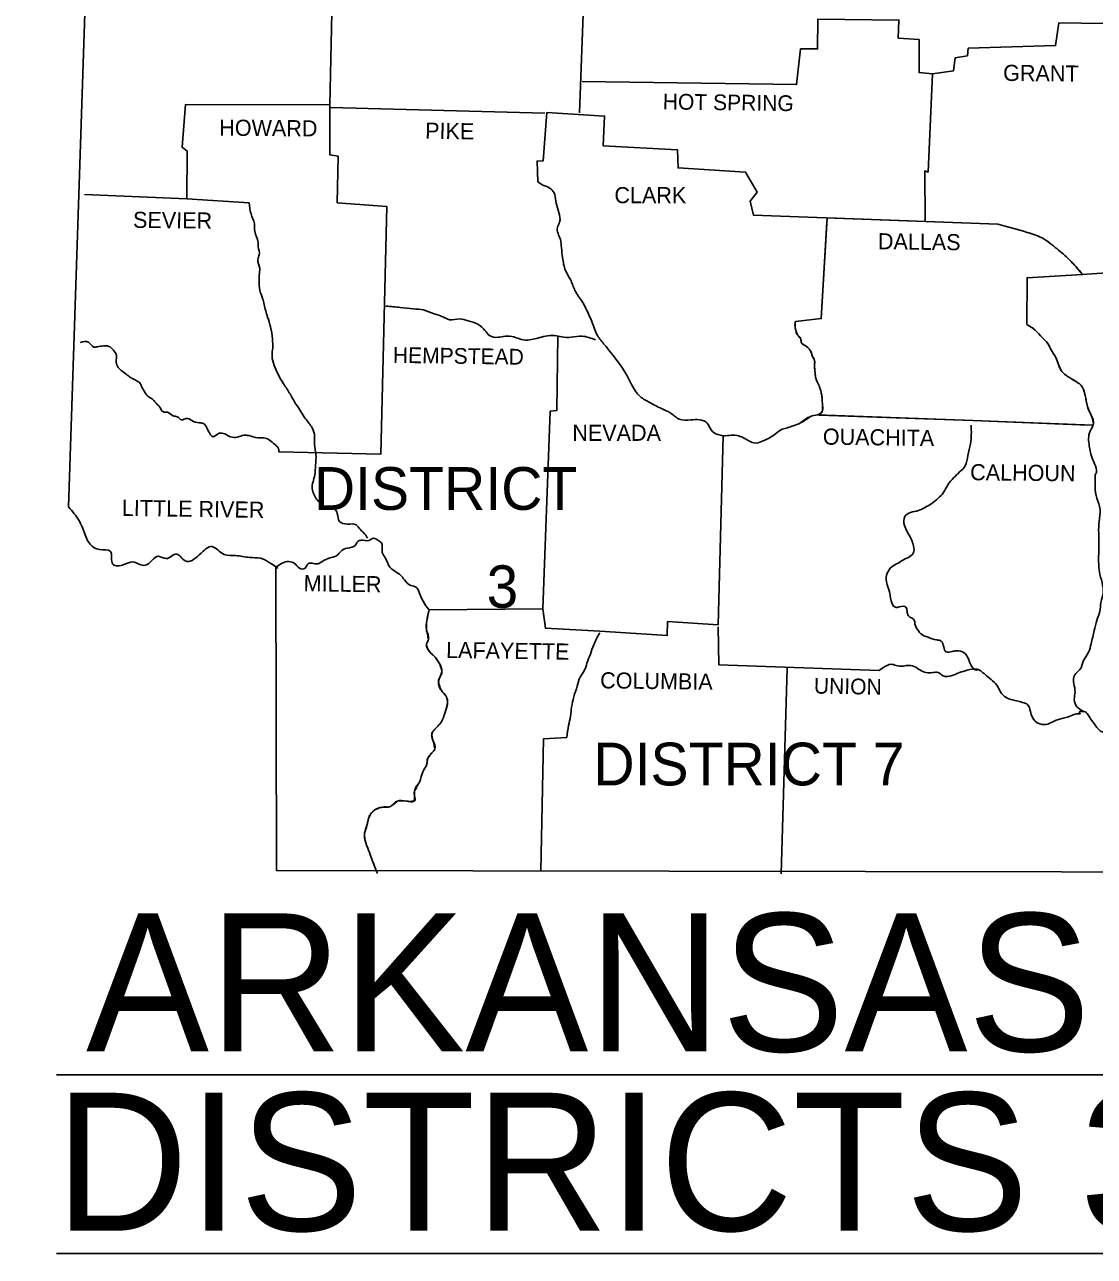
# Model space of a CAD drawing. Extents: x -35254 to 17396, y -8913 to 11592.
# Drawn here: x 11395 to 14186, y 3738 to 6952 of the extents above; entities that cross this region are included whole.
import ezdxf

# ---------------------------------------------------------------- set-up
doc = ezdxf.new("R2010")
doc.units = 0
for name, color, linetype in [('1', 7, 'Continuous'), ('2', 7, 'Continuous'), ('3', 7, 'Continuous'), ('S_MISC_BOUNDARY', 7, 'Continuous')]:
    doc.layers.add(name, color=color, linetype=linetype)

msp = doc.modelspace()

# ---------------------------------------------------------------- linework, layer by layer
at = {"layer": '1'}
for p, q in [((11477.4, 4211.6), (15730.4, 4211.6)), ((11477.4, 3744.7), (15730.4, 3744.7))]:
    msp.add_line(p, q, dxfattribs=at)
for points in [[(11394.6, 9973.9), (11597.1, 8347.8), (11509, 5693.4)], [(12865.1, 7331.3), (12842.6, 6721.7)], [(12201.7, 7223.6), (12191, 6742.3), (11814.3, 6743.2), (11805.5, 6631.7), (11819.2, 6621.9), (11818.2, 6496.7), (11551.1, 6508.4)], [(12849.5, 6802.9), (13409.1, 6795.1), (13419.9, 6888.1), (13463.9, 6888.1), (13464.9, 6966.3), (13676.2, 6963.4), (13674.2, 6916.4), (13729, 6912.5), (13729, 6826.4), (13764.3, 6823.5)], [(13764.3, 6823.5), (13819.1, 6831.3), (13823, 6864.6), (13855.3, 6870.4), (13857.2, 6890), (14085.2, 6896.9), (14094, 6956.5), (14327.8, 6952.6)], [(13764.3, 6823.5), (13752.5, 6567.1), (13743.7, 6570.1), (13744.7, 6437)], [(12191, 6742.3), (12191, 6612.1), (12212.5, 6608.2), (12210.6, 6486.9), (12339.7, 6477.1), (12324, 5830.4), (12057.9, 5837.2)], [(12192.9, 6735.4), (12752.6, 6720.7)], [(12734, 6541.7), (12732, 6595.5), (12747.7, 6596.5), (12757.5, 6722.7), (12908.2, 6712.9), (12904.2, 6635.6), (13098.9, 6624.9), (13099.9, 6577.9), (13276, 6567.1), (13306.4, 6514.3), (13287.8, 6490.8), (13296.6, 6454.6), (13934.5, 6431.1)], [(11818.2, 6496.7), (11980.6, 6486.9)], [(13488.4, 6436), (13473.7, 6184.6), (13406.2, 6176.7)], [(14155.6, 6300), (14010.8, 6291.2), (14009.8, 6168.9)], [(14296.5, 6308.8), (14153.7, 6300)], [(12785.9, 6139.6), (12783.9, 5944.9), (12766.3, 5942.9), (12746.7, 5427.3)], [(13463.9, 5933.1), (13869, 5918.4), (14169.3, 5906.7)], [(13217.3, 5878.3), (13204.6, 5385.2), (13072.5, 5394), (13071.6, 5357.8), (12895.4, 5368.6)], [(12050.1, 5535.9), (12052.1, 4744.4), (15637.9, 4738.5)], [(12895.4, 5368.6), (12753.6, 5376.4), (12746.7, 5427.3), (12450.3, 5424.4)], [(13624.4, 5265.9), (13206.6, 5281.5), (13204.6, 5380.3)], [(13384.6, 5272.7), (13369, 4735.6)], [(12809.3, 5091.7), (12748.7, 5087.8), (12741.8, 4743.4)]]:
    msp.add_lwpolyline(points, dxfattribs=at)
for points in [[(12734, 6541.7), (12749.7, 6531.9), (12768.2, 6523.1), (12778, 6508.4), (12781.9, 6485.9), (12788.8, 6461.5), (12790.7, 6436), (12784.9, 6422.3), (12792.7, 6391), (12795.6, 6369.5), (12798.6, 6344.1), (12806.4, 6309.8), (12819.1, 6286.3), (12830.9, 6258), (12850.4, 6227.6), (12867.1, 6194.4), (12874.9, 6176.7), (12889.6, 6140.5), (12908.2, 6116.1), (12937.5, 6078.9), (12963.9, 6040.8), (12978.6, 6012.4), (13001.1, 5981.1), (13026.5, 5965.4), (13058.8, 5948.8), (13079.4, 5939), (13102.9, 5922.4), (13133.2, 5920.4), (13155.7, 5920.4), (13176.2, 5911.6), (13186, 5894), (13203.6, 5882.2), (13217.3, 5878.3)], [(11980.6, 6486.9), (11985.5, 6457.6), (11994.3, 6432.1), (11995.3, 6412.5), (12004.1, 6383.2), (12004.1, 6372.4), (12007, 6350.9), (12003.1, 6339.2), (12008, 6315.7), (12007, 6298.1), (12007, 6283.4), (12008, 6258.9), (12015.8, 6237.4), (12023.7, 6205.1), (12028.6, 6188.5), (12036.4, 6163.1), (12041.3, 6131.7), (12042.3, 6108.3), (12040.3, 6086.7), (12046.2, 6062.3), (12056.9, 6037.8), (12070.6, 6014.3), (12087.3, 5987.9), (12099, 5967.4), (12113.7, 5944.9), (12125.4, 5926.3), (12143, 5902.8), (12150.9, 5883.2), (12150.9, 5855.8), (12154.8, 5830.4), (12153.8, 5802), (12151.8, 5776.6), (12145, 5741.4), (12149.9, 5724.7), (12168.5, 5700.3), (12180.2, 5693.4), (12200.8, 5689.5), (12210.6, 5675.8), (12216.4, 5655.3), (12237, 5648.4), (12259.5, 5646.5), (12270.2, 5634.7), (12284.9, 5619.1), (12289.8, 5611.2)], [(13934.5, 6431.1), (14010.8, 6409.6), (14050, 6394.9), (14089.1, 6366.6), (14121.4, 6338.2), (14153.7, 6302)], [(12337.7, 6216.9), (12374.9, 6213.9), (12409.2, 6210), (12435.6, 6207.1), (12463, 6197.3), (12487.4, 6188.5), (12503.1, 6181.6), (12529.5, 6183.6), (12552, 6178.7), (12577.5, 6169.9), (12596, 6153.3), (12607.8, 6140.5), (12630.3, 6135.7), (12648.9, 6138.6), (12671.4, 6136.6), (12696.8, 6128.8), (12717.4, 6129.8), (12734, 6133.7), (12753.6, 6138.6), (12778, 6140.5), (12796.6, 6136.6), (12821.1, 6135.7), (12849.5, 6138.6), (12884.7, 6128.8)], [(13406.2, 6176.7), (13406.2, 6158.2), (13413, 6140.5), (13419.9, 6132.7), (13422.8, 6120), (13431.6, 6114.1), (13444.3, 6102.4), (13451.2, 6085.8), (13456.1, 6075), (13456.1, 6061.3), (13457, 6047.6), (13459, 6031), (13470.7, 6001.6), (13473.7, 5989.9), (13475.6, 5980.1), (13476.6, 5963.5), (13476.6, 5943.9), (13463.9, 5933.1)], [(14009.8, 6168.9), (14032.3, 6154.2), (14050.9, 6134.7), (14064.6, 6120), (14073.4, 6103.4), (14085.2, 6083.8), (14101.8, 6046.6), (14116.5, 6033.9), (14137, 6021.2), (14149.8, 6012.4), (14162.5, 5984), (14168.3, 5955.6), (14179.1, 5930.2), (14184, 5910.6), (14175.2, 5891.1), (14173.2, 5851.9), (14179.1, 5825.5), (14186.9, 5805.9), (14191.8, 5783.4), (14188.9, 5776.6)], [(11539.4, 6122), (11560.9, 6122.9), (11575.6, 6110.2), (11584.4, 6111.2), (11600, 6113.2), (11614.7, 6112.2), (11625.5, 6103.4), (11634.3, 6087.7), (11633.3, 6073), (11634.3, 6067.2), (11641.1, 6054.4), (11652.9, 6044.7), (11665.6, 6034.9), (11677.3, 6027.1), (11696.9, 6014.3), (11698.8, 6010.4), (11706.7, 5994.8), (11716.5, 5982), (11728.2, 5974.2), (11740.9, 5960.5), (11746.8, 5954.7), (11756.6, 5941), (11767.3, 5940), (11782, 5931.2), (11792.8, 5928.2), (11804.5, 5920.4), (11816.3, 5924.3), (11830.9, 5918.4), (11850.5, 5912.6), (11861.3, 5910.6), (11874, 5892), (11886.7, 5876.4), (11902.4, 5885.2), (11931.7, 5876.4), (11950.3, 5875.4), (11966.9, 5880.3), (11979.6, 5879.3), (12003.1, 5873.4), (12017.8, 5873.4), (12033.5, 5867.6), (12048.1, 5855.8), (12057.9, 5843.1), (12057.9, 5837.2)], [(13445.3, 5929.2), (13419.9, 5912.6), (13400.3, 5904.8), (13385.6, 5899.9), (13371.9, 5895.9), (13354.3, 5884.2), (13340.6, 5874.4), (13322, 5865.6), (13304.4, 5859.7), (13282.9, 5866.6), (13271.1, 5873.4), (13258.4, 5878.3), (13217.3, 5878.3)], [(13419.9, 5912.6), (13445.3, 5929.2), (13463.9, 5933.1)], [(13865, 5906.7), (13863.1, 5857.8), (13856.2, 5827.5), (13849.4, 5800.1), (13834.7, 5784.4), (13819.1, 5768.8), (13804.4, 5751.1), (13791.7, 5729.6), (13778.9, 5715.9), (13762.3, 5702.2), (13745.7, 5692.4), (13727.1, 5683.6), (13706.5, 5678.7), (13691.9, 5668), (13690.9, 5644.5), (13707.5, 5611.2), (13713.4, 5595.6), (13715.3, 5577), (13708.5, 5566.2), (13692.8, 5557.4), (13674.2, 5546.7), (13657.6, 5536.9), (13645.9, 5520.2), (13643.9, 5497.7), (13651.7, 5471.3), (13654.7, 5455.7), (13667.4, 5431.2), (13677.2, 5432.2), (13694.8, 5431.2), (13696.8, 5426.3), (13697.7, 5421.4), (13701.6, 5408.7), (13716.3, 5397.9), (13718.3, 5388.2), (13727.1, 5369.6), (13741.8, 5356.8), (13752.5, 5352.9), (13775, 5346.1), (13786.8, 5343.1), (13799.5, 5314.8), (13815.1, 5315.8), (13826.9, 5317.7), (13846.4, 5312.8), (13855.3, 5301.1), (13864.1, 5281.5), (13875.8, 5267.8), (13883.6, 5267.8)], [(14188.9, 5776.6), (14192.8, 5715.9), (14201.6, 5686.6), (14198.7, 5655.3), (14197.7, 5624.9), (14197.7, 5597.5), (14197.7, 5571.1), (14197.7, 5543.7), (14199.7, 5524.2), (14206.5, 5495.8), (14209.4, 5469.4), (14203.6, 5443.9), (14200.6, 5420.4), (14192.8, 5397), (14186, 5370.5), (14178.1, 5336.3), (14171.3, 5313.8), (14157.6, 5290.3), (14148.8, 5268.8), (14135.1, 5255.1), (14133.1, 5231.6), (14136.1, 5210.1), (14134.1, 5190.5), (14140.9, 5171.9), (14158.6, 5159.2)], [(11509, 5693.4), (11537.4, 5656.2), (11549.1, 5629.8), (11565.8, 5595.6), (11590.2, 5581.9), (11618.6, 5577), (11624.5, 5543.7), (11653.8, 5542.7), (11677.3, 5549.6), (11709.6, 5540.8), (11743.9, 5564.3), (11763.4, 5558.4), (11791.8, 5570.1), (11813.3, 5552.5), (11850.5, 5568.2), (11883.8, 5589.7), (11915.1, 5569.2), (11945.4, 5566.2), (11981.6, 5561.3), (12010, 5559.4), (12035.4, 5546.7), (12054, 5533.9), (12050.1, 5535.9)], [(12050.1, 5535.9), (12084.3, 5550.6), (12099, 5545.7), (12111.7, 5533), (12126.4, 5533), (12134.2, 5544.7), (12148.9, 5545.7), (12160.7, 5544.7), (12173.4, 5552.5), (12184.1, 5557.4), (12198.8, 5562.3), (12209.6, 5566.2), (12219.4, 5577), (12237, 5585.8), (12257.5, 5592.6), (12263.4, 5602.4), (12273.2, 5606.3), (12292.7, 5605.4), (12305.5, 5611.2), (12316.2, 5606.3), (12326, 5599.5), (12328, 5574.1), (12335.8, 5560.4), (12347.5, 5535.9), (12364.2, 5523.2), (12379.8, 5510.5), (12385.7, 5502.6), (12402.3, 5488), (12417, 5483.1), (12423.8, 5472.3), (12434.6, 5446.9), (12450.3, 5424.4)], [(12450.3, 5424.4), (12444.4, 5396), (12443.4, 5373.5), (12448.3, 5347.1), (12443.4, 5334.3), (12451.2, 5315.8), (12465.9, 5301.1), (12476.7, 5285.4), (12483.5, 5262.9), (12474.7, 5237.5), (12484.5, 5211.1), (12493.3, 5201.3), (12498.2, 5185.6), (12491.4, 5155.3), (12482.5, 5132.8), (12463, 5110.3), (12457.1, 5099.5), (12460, 5084.8), (12464.9, 5061.4), (12460, 5054.5), (12447.3, 5037.9), (12443.4, 5019.3), (12434.6, 5003.6), (12424.8, 4975.3), (12412.1, 4951.8), (12410.1, 4925.4), (12390.6, 4925.4), (12368.1, 4925.4), (12347.5, 4910.7), (12328.9, 4909.7), (12306.4, 4900.9), (12292.7, 4882.3), (12287.8, 4861.8), (12282, 4842.2), (12287.8, 4808.9), (12296.7, 4785.5), (12303.5, 4766.9), (12315.2, 4736.5)], [(12809.3, 5091.7), (12814.2, 5123), (12819.1, 5147.5), (12822.1, 5170.9), (12827.9, 5197.4), (12836.7, 5225.7), (12844.6, 5249.2), (12855.3, 5265.9), (12862.2, 5285.4), (12871, 5308.9), (12879.8, 5333.4), (12895.4, 5364.7)], [(13624.4, 5265.9), (13640, 5276.6), (13654.7, 5282.5), (13669.4, 5279.5), (13685, 5277.6), (13698.7, 5279.5), (13716.3, 5276.6), (13731, 5267.8), (13747.6, 5261), (13764.3, 5261), (13778.9, 5261), (13791.7, 5252.2), (13815.1, 5253.1), (13834.7, 5261), (13854.3, 5266.8), (13880.7, 5269.8), (13904.2, 5253.1), (13920.8, 5239.4), (13934.5, 5223.8), (13944.3, 5206.2), (13955.1, 5196.4), (13972.7, 5189.5), (13986.4, 5186.6), (14003, 5181.7), (14011.8, 5177.8), (14019.6, 5159.2), (14032.3, 5133.8), (14056.8, 5125), (14087.1, 5136.7), (14111.6, 5143.6), (14129.2, 5149.4), (14140, 5153.3), (14149.8, 5154.3), (14146.8, 5156.3), (14158.6, 5159.2), (14169.3, 5151.4), (14176.2, 5140.6), (14187.9, 5125), (14198.7, 5111.3), (14209.4, 5106.4), (14220.2, 5112.2), (14234.9, 5107.4), (14247.6, 5102.5), (14262.3, 5098.5), (14275, 5097.6), (14291.6, 5093.7), (14304.3, 5086.8), (14316.1, 5080), (14327.8, 5067.2), (14339.6, 5047.7), (14343.5, 5032), (14357.2, 5016.4), (14369.9, 5016.4), (14388.5, 4990.9), (14395.3, 4981.1), (14410, 4963.5), (14420.8, 4963.5), (14441.3, 4959.6)]]:
    msp.add_spline(points, degree=3, dxfattribs=at)
at = {"layer": 'S_MISC_BOUNDARY'}
for points in [[(13934.5, 6431.1), (13489, 6447.5), (13473.7, 6184.6), (13406.2, 6176.7)], [(14009.8, 6168.9), (14010.8, 6291.2), (14155.6, 6300)], [(13468.5, 5933), (13869, 5918.4), (14183.1, 5906.2)], [(12050.1, 5535.9), (12052.1, 4744.4), (12312.3, 4743.9)]]:
    msp.add_lwpolyline(points, dxfattribs=at)
for points in [[(14155.6, 6300), (14121.4, 6338.2), (14089.1, 6366.6), (14050, 6394.9), (14010.8, 6409.6), (13934.5, 6431.1)], [(13406.2, 6176.7), (13405.1, 6167.5), (13405.4, 6162.8), (13406.2, 6158.2), (13407.3, 6153.6), (13408.9, 6149.1), (13410.8, 6144.8), (13413, 6140.5), (13414.6, 6138.4), (13416.4, 6136.5), (13418.3, 6134.7), (13419.9, 6132.7), (13420.8, 6129.7), (13421, 6126.2), (13421.3, 6122.8), (13421.9, 6121.3), (13422.8, 6120), (13424.9, 6118.3), (13427.1, 6117), (13429.4, 6115.6), (13431.6, 6114.1), (13433.3, 6112.8), (13435.1, 6111.5), (13438.6, 6108.8), (13441.8, 6105.9), (13443.2, 6104.2), (13444.3, 6102.4), (13446.2, 6098.3), (13447.9, 6094.1), (13449.5, 6089.9), (13451.2, 6085.8), (13453.8, 6080.5), (13455, 6077.8), (13455.6, 6076.4), (13456.1, 6075), (13456.6, 6071.6), (13456.4, 6068.2), (13456.1, 6064.7), (13456.1, 6061.3), (13456.1, 6060.6)], [(14107, 6040.9), (14101.8, 6046.6), (14100.4, 6048.8), (14099.1, 6051), (14096.8, 6055.6), (14093, 6065.1), (14089.5, 6074.6), (14085.2, 6083.8), (14079.3, 6093.6), (14073.4, 6103.4), (14071.3, 6107.6), (14069.4, 6111.9), (14067.3, 6116.2), (14064.6, 6120), (14063, 6121.9), (14061.3, 6123.8), (14057.9, 6127.4), (14050.9, 6134.7), (14032.3, 6154.2), (14027.4, 6158.7), (14021.9, 6162.5), (14016.1, 6165.8), (14009.8, 6168.9)], [(13456.1, 6060.6), (13456.5, 6054.4), (13457, 6047.6), (13457.8, 6039.3), (13458.3, 6035.1), (13459, 6031), (13461.3, 6023.4), (13464.6, 6016.2), (13468, 6009), (13470.7, 6001.6), (13473.7, 5989.9), (13475.6, 5980.1), (13476, 5975.9), (13476.2, 5971.8), (13476.6, 5963.5), (13476.8, 5958.6), (13476.9, 5953.7), (13476.8, 5948.8), (13476.7, 5946.3), (13476.6, 5943.9), (13475.8, 5941.1), (13473.8, 5938.1), (13472.6, 5936.7), (13471.3, 5935.3), (13468.5, 5933)], [(14183.1, 5906.2), (14184, 5910.6), (14183.4, 5915.5), (14182.3, 5920.4), (14179.1, 5930.2), (14176.4, 5936.6), (14173.6, 5942.9), (14170.8, 5949.2), (14168.3, 5955.6), (14166.5, 5962.6), (14165.2, 5969.7), (14164.1, 5976.9), (14162.5, 5984), (14160.4, 5991.7), (14158.1, 5999.2), (14154.7, 6006.3), (14149.8, 6012.4), (14148.2, 6013.7), (14146.7, 6014.9), (14143.5, 6017.1), (14137, 6021.2), (14116.5, 6033.9), (14108.5, 6039.6), (14107, 6040.9)], [(12450.3, 5424.4), (12434.6, 5446.9), (12423.8, 5472.3), (12417, 5483.1), (12402.3, 5488), (12385.7, 5502.6), (12379.8, 5510.5), (12364.2, 5523.2), (12347.5, 5535.9), (12335.8, 5560.4), (12328, 5574.1), (12326, 5599.5), (12316.2, 5606.3), (12305.5, 5611.2), (12292.7, 5605.4), (12273.2, 5606.3), (12263.4, 5602.4), (12257.5, 5592.6), (12237, 5585.8), (12219.4, 5577), (12209.6, 5566.2), (12198.8, 5562.3), (12184.1, 5557.4), (12173.4, 5552.5), (12160.7, 5544.7), (12148.9, 5545.7), (12134.2, 5544.7), (12126.4, 5533), (12111.7, 5533), (12099, 5545.7), (12084.3, 5550.6), (12050.1, 5535.9)], [(12475.3, 5233.6), (12474.7, 5237.5), (12475.8, 5243.8), (12479.1, 5250.2), (12482.4, 5256.6), (12483.5, 5262.9), (12482.7, 5268.5), (12481.3, 5274.2), (12479.3, 5279.8), (12476.7, 5285.4), (12471.6, 5293.6), (12465.9, 5301.1), (12462.4, 5304.8), (12458.6, 5308.1), (12454.8, 5311.6), (12451.2, 5315.8), (12446, 5325), (12444.3, 5329.6), (12443.4, 5334.3), (12444, 5337.5), (12445.8, 5340.7), (12447.6, 5343.8), (12448.3, 5347.1), (12447.3, 5353.5), (12445.7, 5360.1), (12444.1, 5366.8), (12443.4, 5373.5), (12444.4, 5396), (12445.5, 5403.7), (12446.9, 5411.8), (12450.3, 5424.4)], [(12455, 5048), (12460, 5054.5), (12461.5, 5056.2), (12463.1, 5057.8), (12464.9, 5061.4), (12464.9, 5062.8), (12464.7, 5064.3), (12464.3, 5067.2), (12463, 5073.1), (12461.5, 5079), (12460, 5084.8), (12458.3, 5092.2), (12457.6, 5095.9), (12457.3, 5097.7), (12457.1, 5099.5), (12463, 5110.3), (12467.9, 5116.1), (12473.2, 5121.3), (12478.3, 5126.7), (12480.5, 5129.6), (12482.5, 5132.8), (12491.4, 5155.3), (12495.7, 5170.5), (12497.3, 5178), (12498.2, 5185.6), (12493.3, 5201.3), (12491.3, 5204), (12489, 5206.2), (12486.6, 5208.4), (12484.5, 5211.1), (12478.1, 5224.2), (12476, 5230.8), (12475.3, 5233.6)], [(12343.3, 4910.1), (12347.5, 4910.7), (12352.9, 4913.8), (12357.6, 4918.8), (12362.4, 4923.4), (12368.1, 4925.4), (12390.6, 4925.4), (12410.1, 4925.4), (12412.6, 4926.2), (12413.7, 4928.4), (12413, 4935.6), (12411.5, 4944.4), (12412.1, 4951.8), (12415.2, 4957.6), (12418.6, 4963.4), (12422, 4969.3), (12424.8, 4975.3), (12427.4, 4982.3), (12429.7, 4989.5), (12432, 4996.6), (12434.6, 5003.6), (12436.6, 5007.6), (12439, 5011.5), (12441.3, 5015.3), (12443.4, 5019.3), (12444.6, 5023.9), (12445, 5028.8), (12445.5, 5033.6), (12447.3, 5037.9), (12453.6, 5046.2), (12455, 5048)], [(12312.3, 4743.9), (12303.5, 4766.9), (12296.7, 4785.5), (12287.8, 4808.9), (12285, 4817.1), (12282.7, 4825.5), (12281.5, 4833.9), (12282, 4842.2), (12284.7, 4852), (12286.4, 4856.9), (12287.8, 4861.8), (12289.2, 4866.9), (12290.3, 4872), (12291.4, 4877.2), (12292.7, 4882.3), (12297.9, 4892.5), (12301.8, 4896.9), (12306.4, 4900.9), (12317.4, 4906.6), (12328.9, 4909.7), (12333.6, 4910.2), (12338.3, 4910.2), (12343, 4910.1), (12343.3, 4910.1)]]:
    msp.add_spline(points, degree=3, dxfattribs=at)

# ---------------------------------------------------------------- texts
at = {"layer": '2'}
for s, height, rotation, p in [('GRANT', 42.07, 359.4032, (13948.2, 6804.9)), ('HOT SPRING', 41.09, 359.2216, (13059.8, 6730.5)), ('HOWARD', 42.07, 359.5145, (11902.4, 6662)), ('PIKE', 42.06, 359.0452, (12439.5, 6654.2)), ('SEVIER', 42.07, 359.4271, (11677.3, 6421.4)), ('DALLAS', 42.06, 359.2462, (13621.4, 6365.6)), ('HEMPSTEAD', 41.08, 359.1885, (12355.4, 6069.1)), ('OUACHITA', 42.07, 359.2043, (13477.6, 5855.8)), ('CALHOUN', 42.07, 359.3634, (13862.1, 5762.9)), ('LITTLE RIVER', 42.073, 359.1697, (11648, 5669.9)), ('MILLER', 42.06, 359.1319, (12122.5, 5473.3)), ('LAFAYETTE', 42.06, 359.1839, (12494.3, 5299.1)), ('COLUMBIA', 42.06, 359.2125, (12896.4, 5219.9)), ('UNION', 41.09, 358.9584, (13454.1, 5206.2))]:
    msp.add_text(s, height=height, rotation=rotation, dxfattribs=at).set_placement(p)
for s, height, p in [('CLARK', 42.07, (12933.8, 6485.7)), ('NEVADA', 42.07, (12824, 5865.6)), ('ARKANSAS HIGHWAY', 360, (11554.8, 4272.5)), ('DISTRICTS 3 , 4 , 7 , & 8', 360, (11474, 3804.5))]:
    msp.add_text(s, height=height, dxfattribs=at).set_placement(p)
at = {"layer": '3'}
for s, height, p in [('DISTRICT', 111.54, (12149.4, 5685.5)), ('3', 110.6, (12600.4, 5430.1)), ('DISTRICT 7', 111.54, (12878.8, 4966.5))]:
    msp.add_text(s, height=height, dxfattribs=at).set_placement(p)

doc.saveas('drawing.dxf')
